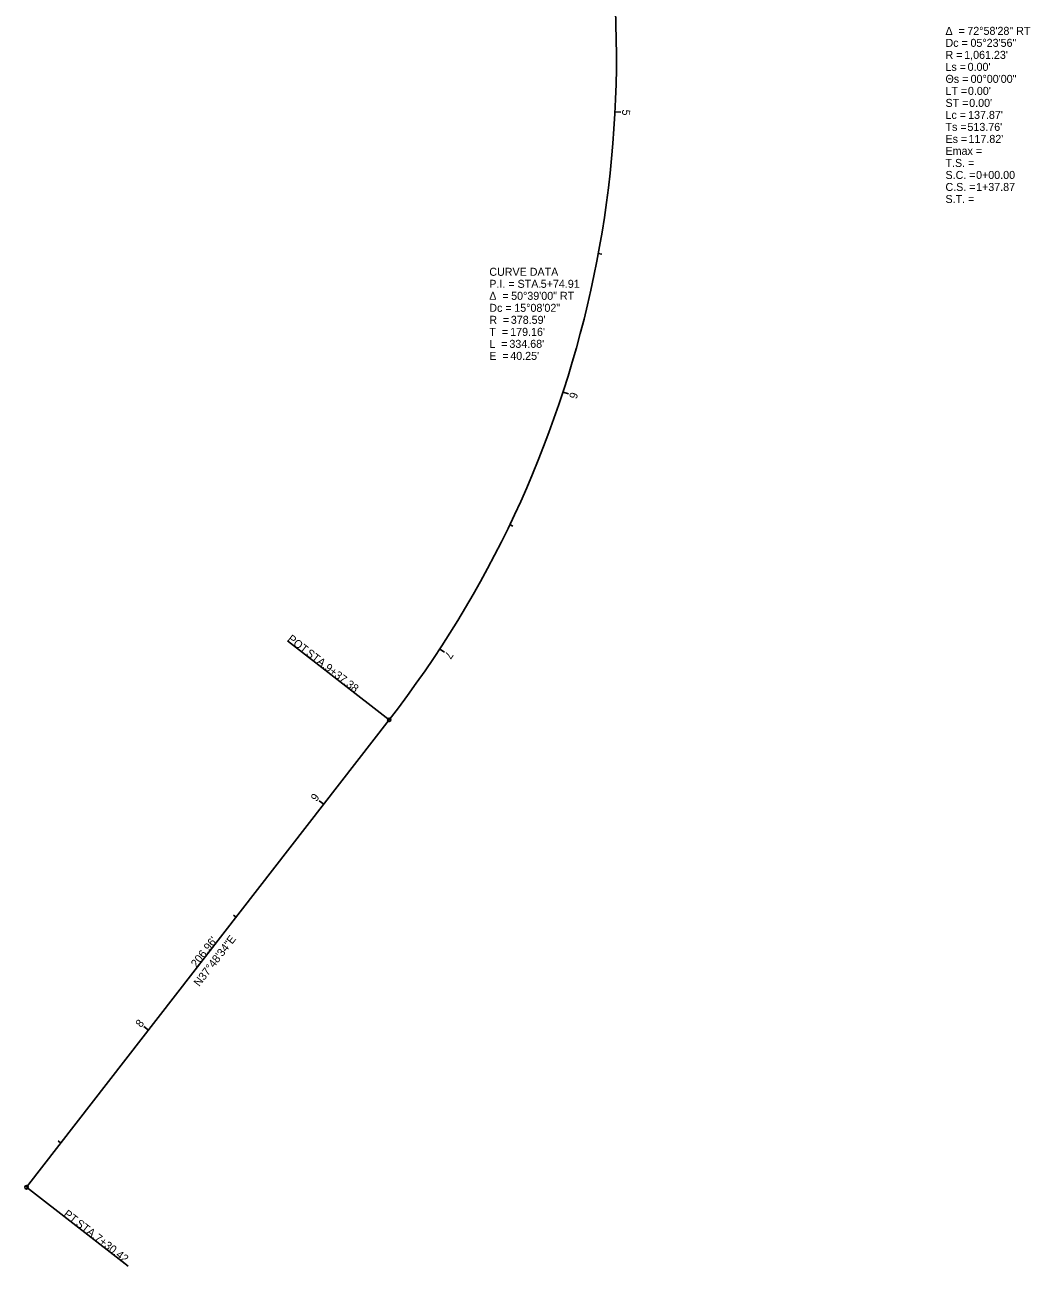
# Model space of a CAD drawing. Extents: x 2376685 to 2377050, y 700343 to 701208.
# Drawn here: x 2376696 to 2377047.7, y 700342.7 to 700776.9 of the extents above; entities that cross this region are included whole.
import ezdxf

# ---------------------------------------------------------------- set-up
doc = ezdxf.new("R2010")
doc.units = 0
for name, color, linetype in [('GE_X_Alignment', 7, 'Continuous'), ('GE_X_Alignment_100_Bearings', 7, 'Continuous'), ('GE_X_Alignment_100_Cardinal_Points', 7, 'Continuous'), ('GE_X_Alignment_100_Curve_Data', 7, 'Continuous'), ('GE_X_Alignment_100_Distances', 7, 'Continuous'), ('GE_X_Alignment_100_Stations', 7, 'Continuous')]:
    doc.layers.add(name, color=color, linetype=linetype)

msp = doc.modelspace()

# ---------------------------------------------------------------- linework, layer by layer
at = {"layer": 'GE_X_Alignment'}
msp.add_line((2376696.61, 700370.32), (2376823.49, 700533.83), dxfattribs=at)
msp.add_arc((2376524.38, 700765.92), 378.59, 322.1906, 12.8405, dxfattribs=at)
at = {"layer": 'GE_X_Alignment_100_Cardinal_Points'}
for p, q in [((2376823.49, 700533.83), (2376787.93, 700561.42)), ((2376696.61, 700370.32), (2376732.17, 700342.74))]:
    msp.add_line(p, q, dxfattribs=at)
for centre in [(2376823.49, 700533.83), (2376696.61, 700370.32)]:
    msp.add_circle(centre, 0.6, dxfattribs=at)
at = {"layer": 'GE_X_Alignment_100_Stations'}
for p, q in [((2376902.47, 700746.52), (2376904.47, 700746.42)), ((2376896.63, 700696.9), (2376897.81, 700696.68)), ((2376884.3, 700648.48), (2376886.2, 700647.86)), ((2376865.7, 700602.11), (2376866.78, 700601.59)), ((2376841.15, 700558.59), (2376842.83, 700557.5)), ((2376800.57, 700504.3), (2376798.99, 700505.52)), ((2376769.92, 700464.8), (2376768.97, 700465.53)), ((2376739.27, 700425.29), (2376737.69, 700426.52)), ((2376708.62, 700385.79), (2376707.67, 700386.53))]:
    msp.add_line(p, q, dxfattribs=at)

# ---------------------------------------------------------------- texts
at = {"layer": 'GE_X_Alignment_100_Bearings'}
msp.add_text('N37°48\'34"E', height=2.8, rotation=52.1906, dxfattribs=at).set_placement((2376757.03, 700440.35))
at = {"layer": 'GE_X_Alignment_100_Cardinal_Points'}
for s, p in [('POT', (2376787.68, 700561.66)), (' STA. ', (2376793.32, 700557.29)), ('9+37.38', (2376800.68, 700551.58)), ('PT', (2376709.34, 700360.5)), (' STA. ', (2376712.78, 700357.83)), ('7+30.42', (2376720.14, 700352.11))]:
    msp.add_text(s, height=2.8, rotation=322.1906, dxfattribs=at).set_placement(p)
at = {"layer": 'GE_X_Alignment_100_Curve_Data'}
for s, p in [('Δ  = ', (2377018.09, 700773.42)), ('72°58\'28" RT', (2377025.73, 700773.42)), ('Dc = ', (2377018.09, 700769.22)), ('05°23\'56"', (2377026.83, 700769.22)), ('R = ', (2377018.09, 700765.02)), ("1,061.23'", (2377024.63, 700765.02)), ('Θs = ', (2377018.09, 700756.62)), ('Ls = ', (2377018.09, 700760.82)), ("0.00'", (2377025.83, 700760.82)), ('00°00\'00"', (2377026.87, 700756.62)), ('LT = ', (2377018.09, 700752.42)), ("0.00'", (2377025.94, 700752.42)), ('ST = ', (2377018.09, 700748.22)), ("0.00'", (2377026.39, 700748.22)), ('Lc = ', (2377018.09, 700744.02)), ("137.87'", (2377026, 700744.02)), ('Ts = ', (2377018.09, 700739.82)), ("513.76'", (2377025.77, 700739.82)), ('Es = ', (2377018.09, 700735.62)), ("117.82'", (2377026.14, 700735.62)), ('Emax = ', (2377018.09, 700731.42)), ('T.S. = ', (2377018.09, 700727.22)), ('S.C. = ', (2377018.09, 700723.02)), ('0+00.00', (2377028.79, 700723.02)), ('C.S. = ', (2377018.09, 700718.82)), ('1+37.87', (2377028.79, 700718.82)), ('S.T. = ', (2377018.09, 700714.62)), ('CURVE DATA', (2376858.5, 700689.14)), ('P.I. = STA. ', (2376858.5, 700684.94)), ('5+74.91', (2376876.49, 700684.94)), ('Δ  = ', (2376858.5, 700680.74)), ('50°39\'00" RT', (2376866.14, 700680.74)), ('Dc = ', (2376858.5, 700676.54)), ('15°08\'02"', (2376867.24, 700676.54)), ('R  = ', (2376858.5, 700672.34)), ("378.59'", (2376866.03, 700672.34)), ('T  = ', (2376858.5, 700668.14)), ("179.16'", (2376865.81, 700668.14)), ('L  = ', (2376858.5, 700663.94)), ("334.68'", (2376865.53, 700663.94)), ('E  = ', (2376858.5, 700659.74)), ("40.25'", (2376865.84, 700659.74))]:
    msp.add_text(s, height=2.8, dxfattribs=at).set_placement(p)
at = {"layer": 'GE_X_Alignment_100_Distances'}
msp.add_text("206.96'", height=2.8, rotation=52.1906, dxfattribs=at).set_placement((2376756.07, 700447.01))
at = {"layer": 'GE_X_Alignment_100_Stations'}
for s, rotation, p in [('5', 267.0627, (2376905.02, 700747.36)), ('6', 251.9287, (2376886.99, 700648.68)), ('7', 236.7947, (2376843.8, 700558.06)), ('9', 52.1906, (2376797.99, 700505.05)), ('8', 52.1906, (2376736.67, 700426.02))]:
    msp.add_text(s, height=2.8, rotation=rotation, dxfattribs=at).set_placement(p)

doc.saveas('drawing.dxf')
